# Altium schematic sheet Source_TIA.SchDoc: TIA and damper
size A4; Author: Watzek; DrawnBy: Watzek; Organization: HTL Hollabrunn; Address1: Abteilung Elektronik; Address2: Anton Ehrenfried-Straße 10; Address3: 2020 Hollabrunn; DocumentNumber: 02; Revision: 01; SheetNumber: 02; SheetTotal: 02; SPICEModelCacheBSQSHVBX: <root> / <DocumentId>BSQSHVBX</DocumentId> / <CacheFrame Number="0"> / <Model Name="cap" Kind="MDL"> / <Text>*Default semiconductor capacitor / .MODEL CAP C()</Text> / </Model> / </CacheFrame> / </root>
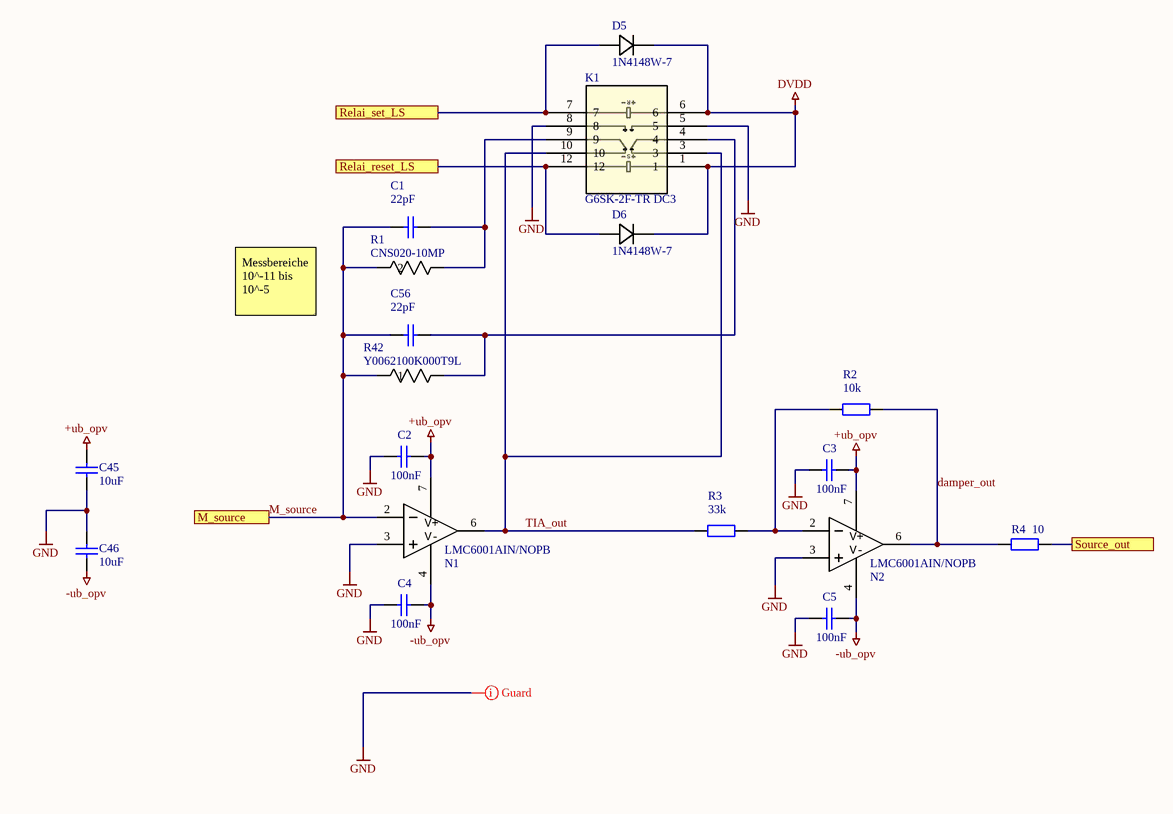
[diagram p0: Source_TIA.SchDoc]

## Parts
C1  22pF  [C1206-KUE]
C2  100nF  [C1206-KUE]
C3  100nF  [C1206-KUE]
C4  100nF  [C1206-KUE]
C5  100nF  [C1206-KUE]
C45  10uF  [C1206-KUE]
C46  10uF  [C1206-KUE]
C56  22pF  [C1206-KUE]
D5  1N4148W-7  [SOD123_DIO]
D6  1N4148W-7  [SOD123_DIO]
K1  G6SK-2F-TR DC3  [RELAY_G6SK-2F DC3_OMR]
N1  LMC6001AIN/NOPB  [DIP8]
N2  LMC6001AIN/NOPB  [DIP8]
R1  CNS020-10MP  [RES_CNS020_VIS]
R2  10k  [C1206-KUE]
R3  33k  [C1206-KUE]
R4  10  [C1206-KUE]
R42  Y0062100K000T9L  [RES_S102K_7P62X2P67_VIS]

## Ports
M_source, Relai_reset_LS, Relai_set_LS, Source_out

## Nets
+ub_opv: C2.2 C3.2 C45.2 N1.7(V+) N2.7(V+)
-ub_opv: C4.2 C5.2 C46.1 N1.4(V-) N2.4(V-)
DVDD: D5.1 D6.1 K1.1 K1.6
GND: C2.1 C3.1 C4.1 C5.1 C45.1 C46.2 K1.5 K1.8 N1.3(IN+) N2.3(IN+)
damper_out: N2.6(OUT) R2.1 R4.2
M_source: C1.1 C56.1 N1.2(IN-) R1.2 R42.1 ; port M_source
Relai_reset_LS: D6.2 K1.12 ; port Relai_reset_LS
Relai_set_LS: D5.2 K1.7 ; port Relai_set_LS
Source_out: R4.1 ; port Source_out
TIA_out: K1.3 K1.10 N1.6(OUT) R3.2
NetC1_2: C1.2 K1.9 R1.1
NetC56_2: C56.2 K1.4 R42.2
NetN2_2: N2.2(IN-) R2.2 R3.1

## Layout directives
mark named Guard: GND

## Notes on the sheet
- Messbereiche 10^-11 bis 10^-5

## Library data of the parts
C1-C5 C45 C46 C56 = Capacitor: Manufacturer: Kemet; Bezeichnung: Kerko +-10% 63V
D5 D6 = 1N4148W-7: Description; Manufacturer_Name: Diodes Inc
K1 = G6SK-2F-TR DC3: Description; Manufacturer_Name: Omron
N1 N2 = LMC6001AINNOPB: Ultra-Low Input Current Amplifier 8-PDIP -40 to 85; Manufacturer_Name: Texas Instruments; Manufacturer: NationalSemiconductor; Characteristics: LMC6001AINUltra-LowInputBiasCurrentOpAmp; CompType: OpAmpIC; TaMin_C: -400; TaMax_C: 850; ComponentLink1DescBC: LMC6001Datasheet; ComponentLink2DescA4: LMC6001WebPage; ComponentLink3DescAC: N08EPackageWebPage
R1 = CNS020-10KP: CNS 020 10K 0,02% e2; Manufacturer_Name: Vishay
R2-R4 = ResistorSMD: Resistor SMD; Manufacturer: AVX; Bezeichnung: SMD Wid. 1/8W 2%
R42 = Y0062100K000T9L: No Description Available; Manufacturer_Name: Vishay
